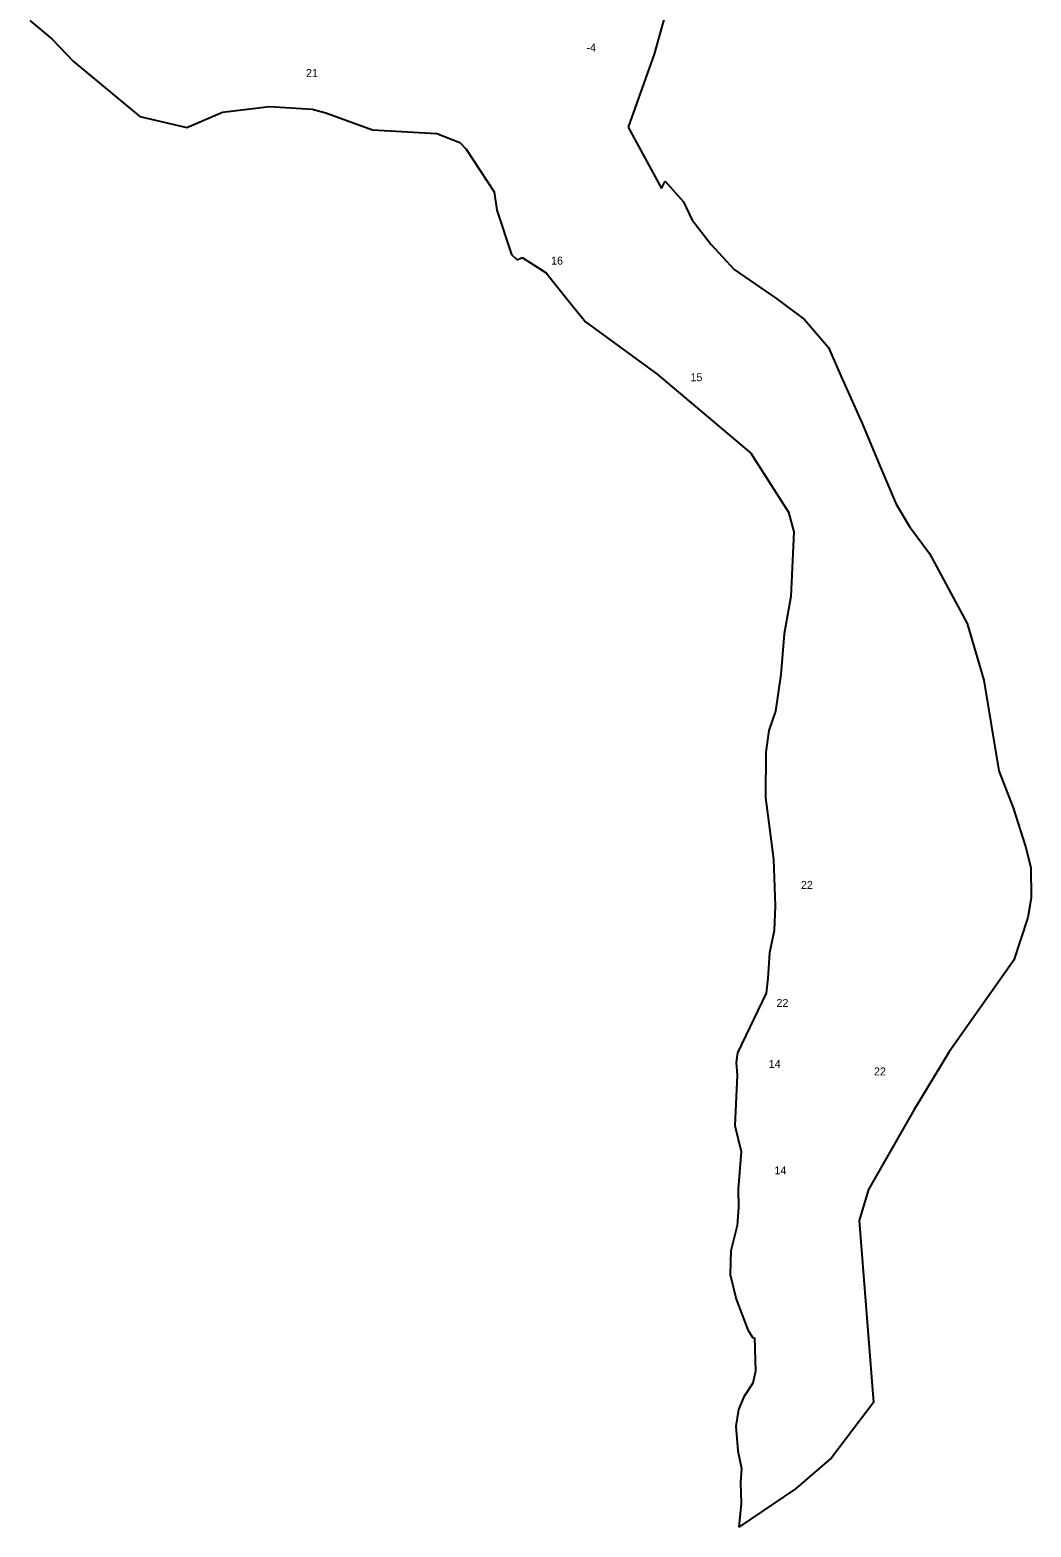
# Model space of a CAD drawing. Extents: x -790660 to -787188, y -969557 to -965825.
# Drawn here: x -788440 to -787188, y -969557 to -967686 of the extents above; entities that cross this region are included whole.
import ezdxf

# ---------------------------------------------------------------- set-up
doc = ezdxf.new("R2010")
doc.units = 0
doc.layers.add('Vrstva 13', color=7, linetype='Continuous')
doc.layers.add('Vrstva 15', color=7, linetype='Continuous')

msp = doc.modelspace()

# ---------------------------------------------------------------- linework, layer by layer
at = {"layer": 'Vrstva 13'}
for p, q in [((-787644.24, -967662.92), (-787659.59, -967716.75)), ((-788439.62, -967674.68), (-788411.95, -967698.02)), ((-788411.95, -967698.02), (-788385.3, -967725.71)), ((-787659.59, -967716.75), (-787692.02, -967808.05)), ((-788385.3, -967725.71), (-788302.29, -967794.41)), ((-788302.29, -967794.41), (-788243.62, -967808.42)), ((-788243.62, -967808.42), (-788198.95, -967789.07)), ((-788198.95, -967789.07), (-788140.28, -967782.07)), ((-788140.28, -967782.07), (-788086.95, -967785.41)), ((-788086.95, -967785.41), (-788069.62, -967790.08)), ((-788069.62, -967790.08), (-788011.61, -967811.09)), ((-788011.61, -967811.09), (-787930.94, -967815.75)), ((-787930.94, -967815.75), (-787902.27, -967827.09)), ((-787692.02, -967808.05), (-787650.12, -967884.42)), ((-787902.27, -967827.09), (-787894.28, -967835.43)), ((-787894.28, -967835.43), (-787859.28, -967888.78)), ((-787859.28, -967888.78), (-787856.28, -967911.79)), ((-787650.12, -967884.42), (-787645.81, -967875.23)), ((-787645.81, -967875.23), (-787622.57, -967901.36)), ((-787622.57, -967901.36), (-787612.52, -967923.18)), ((-787856.28, -967911.79), (-787837.94, -967966.82)), ((-787612.52, -967923.18), (-787588.7, -967954.18)), ((-787837.94, -967966.82), (-787830.84, -967973.57)), ((-787588.7, -967954.18), (-787559.43, -967985.76)), ((-787830.84, -967973.57), (-787824.45, -967970.7)), ((-787824.45, -967970.7), (-787794.43, -967989.87)), ((-787559.43, -967985.76), (-787506.05, -968022.23)), ((-787794.43, -967989.87), (-787766.97, -968024.69)), ((-787506.05, -968022.23), (-787471.33, -968048.07)), ((-787766.97, -968024.69), (-787745.25, -968051.21)), ((-787745.25, -968051.21), (-787655.51, -968116.38)), ((-787471.33, -968048.07), (-787441.48, -968083.09)), ((-787441.48, -968083.09), (-787425.98, -968118.69)), ((-787655.51, -968116.38), (-787538.63, -968215.42)), ((-787425.98, -968118.69), (-787399, -968178.98)), ((-787399, -968178.98), (-787377.19, -968230.95)), ((-787538.63, -968215.42), (-787491.37, -968288.89)), ((-787377.19, -968230.95), (-787356.82, -968278.89)), ((-787356.82, -968278.89), (-787340.17, -968307.03)), ((-787491.37, -968288.89), (-787484.66, -968313.81)), ((-787484.66, -968313.81), (-787488.81, -968394.64)), ((-787340.17, -968307.03), (-787315.21, -968340.62)), ((-787315.21, -968340.62), (-787268.43, -968428.18)), ((-787488.81, -968394.64), (-787496.8, -968441.28)), ((-787268.43, -968428.18), (-787247.48, -968499.1)), ((-787496.8, -968441.28), (-787500.96, -968491.75)), ((-787500.96, -968491.75), (-787507.66, -968537.76)), ((-787247.48, -968499.1), (-787228.83, -968612.21)), ((-787507.66, -968537.76), (-787516.28, -968562.04)), ((-787516.28, -968562.04), (-787519.8, -968589.19)), ((-787519.8, -968589.19), (-787520.12, -968645.74)), ((-787228.83, -968612.21), (-787210.76, -968658.72)), ((-787520.12, -968645.74), (-787510.22, -968722.74)), ((-787210.76, -968658.72), (-787195.26, -968706.95)), ((-787195.26, -968706.95), (-787188.66, -968733.08)), ((-787510.22, -968722.74), (-787508.3, -968780.88)), ((-787188.66, -968733.08), (-787188.37, -968770.98)), ((-787188.37, -968770.98), (-787192.38, -968795.67)), ((-787508.3, -968780.88), (-787509.26, -968811.87)), ((-787192.38, -968795.67), (-787209.89, -968849.07)), ((-787509.26, -968811.87), (-787515.33, -968839.67)), ((-787515.33, -968839.67), (-787517.56, -968871.3)), ((-787209.89, -968849.07), (-787290.81, -968963.32)), ((-787517.56, -968871.3), (-787519.48, -968890.15)), ((-787519.48, -968890.15), (-787555.25, -968964.91)), ((-787555.25, -968964.91), (-787556.84, -968977.05)), ((-787556.84, -968977.05), (-787555.89, -968992.7)), ((-787290.81, -968963.32), (-787335.01, -969036.24)), ((-787555.89, -968992.7), (-787558.76, -969055.64)), ((-787335.01, -969036.24), (-787391.69, -969135.44)), ((-787558.76, -969055.64), (-787550.77, -969088.22)), ((-787550.77, -969088.22), (-787554.29, -969135.18)), ((-787554.29, -969135.18), (-787553.97, -969158.19)), ((-787391.69, -969135.44), (-787403.17, -969174.48)), ((-787553.97, -969158.19), (-787555.56, -969180.55)), ((-787555.56, -969180.55), (-787563.55, -969212.18)), ((-787403.17, -969174.48), (-787385.38, -969401.86)), ((-787563.55, -969212.18), (-787564.51, -969241.89)), ((-787564.51, -969241.89), (-787556.85, -969272.56)), ((-787556.85, -969272.56), (-787542.48, -969310.9)), ((-787542.48, -969310.9), (-787536.09, -969320.8)), ((-787536.09, -969320.8), (-787533.93, -969320.48)), ((-787533.93, -969320.48), (-787532.81, -969362.49)), ((-787532.81, -969362.49), (-787536.01, -969377.83)), ((-787536.01, -969377.83), (-787547.35, -969394.76)), ((-787547.35, -969394.76), (-787554.22, -969410.72)), ((-787385.38, -969401.86), (-787437.61, -969470.76)), ((-787554.22, -969410.72), (-787557.41, -969431.33)), ((-787557.41, -969431.33), (-787554.86, -969462)), ((-787554.86, -969462), (-787550.24, -969484.2)), ((-787437.61, -969470.76), (-787482.95, -969509.81)), ((-787550.24, -969484.2), (-787551.67, -969501.46)), ((-787551.67, -969501.46), (-787550.87, -969528.13)), ((-787482.95, -969509.81), (-787553.55, -969557.47)), ((-787550.87, -969528.13), (-787553.55, -969557.47))]:
    msp.add_line(p, q, dxfattribs=at)

# ---------------------------------------------------------------- texts
at = {"layer": 'Vrstva 15'}
for s, p in [('-4', (-787744.086, -967713.39)), ('21', (-788094.611, -967745.26)), ('16', (-787788.254, -967979.66)), ('15', (-787614.021, -968125.45)), ('22', (-787475.976, -968759.93)), ('22', (-787506.566, -968907.48)), ('14', (-787516.207, -968983.62)), ('22', (-787384.656, -968993.02)), ('14', (-787509.097, -969116.67))]:
    msp.add_text(s, height=10, dxfattribs=at).set_placement(p)

doc.saveas('drawing.dxf')
